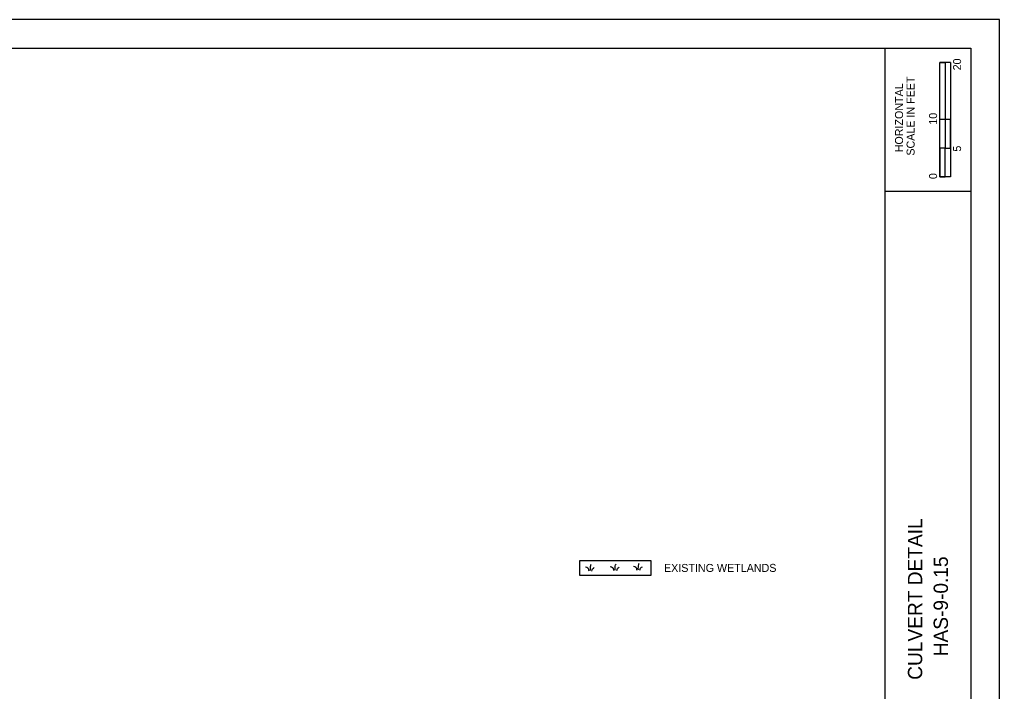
# Model space of a CAD drawing. Extents: x -0.3 to 34, y 0 to 22.
# Drawn here: x 16.87 to 34, y 10.25 to 22 of the extents above; entities that cross this region are included whole.
import ezdxf

# ---------------------------------------------------------------- set-up
doc = ezdxf.new("R2010")
doc.units = 0
for name, color, linetype in [('EV_Ecological_Wetlands', 7, 'Continuous'), ('SH_Border', 7, 'Continuous'), ('SH_Cut_Line', 7, 'Continuous'), ('SH_Data', 7, 'Continuous'), ('SH_Text', 7, 'Continuous')]:
    doc.layers.add(name, color=color, linetype=linetype)

msp = doc.modelspace()

# ---------------------------------------------------------------- linework, layer by layer
at = {"layer": 'EV_Ecological_Wetlands'}
msp.add_lwpolyline([(26.659, 12.535), (26.659, 12.285), (27.909, 12.285), (27.909, 12.535)], close=True, dxfattribs=at)
for points in [[(26.76, 12.43), (26.801, 12.413), (26.819, 12.359)], [(26.847, 12.363), (26.847, 12.411), (26.853, 12.455), (26.862, 12.476)], [(26.875, 12.356), (26.887, 12.395), (26.916, 12.418)], [(27.195, 12.437), (27.236, 12.419), (27.254, 12.366)], [(27.282, 12.37), (27.282, 12.417), (27.288, 12.462), (27.297, 12.483)], [(27.31, 12.363), (27.322, 12.401), (27.351, 12.425)], [(27.599, 12.444), (27.641, 12.426), (27.658, 12.373)], [(27.686, 12.377), (27.686, 12.424), (27.692, 12.469), (27.701, 12.489)], [(27.714, 12.37), (27.726, 12.408), (27.756, 12.432)]]:
    msp.add_spline(points, degree=3, dxfattribs=at)
at = {"layer": 'SH_Border'}
for p, q in [((32, 0.5), (32, 21.5)), ((32, 19), (33.5, 19))]:
    msp.add_line(p, q, dxfattribs=at)
msp.add_lwpolyline([(1.5, 21.5), (33.5, 21.5), (33.5, 0.5), (1.5, 0.5)], close=True, dxfattribs=at)
at = {"layer": 'SH_Cut_Line'}
msp.add_lwpolyline([(0, 0), (34, 0), (34, 22), (0, 22)], close=True, dxfattribs=at)
at = {"layer": 'SH_Data'}
for p, q in [((32.957, 19.25), (32.957, 21.25)), ((33.144, 21.25), (32.957, 21.25)), ((32.957, 20.25), (32.957, 21.25)), ((32.957, 21.25), (33.05, 21.25)), ((33.05, 21.25), (33.051, 21.25)), ((33.051, 21.25), (33.051, 20.25)), ((33.144, 21.25), (33.144, 19.25)), ((33.051, 20.25), (32.957, 20.25)), ((33.143, 20.25), (33.05, 20.25)), ((33.05, 20.25), (33.05, 19.75)), ((33.143, 19.75), (33.143, 20.25)), ((33.05, 19.75), (32.957, 19.75)), ((32.957, 19.75), (32.957, 19.25)), ((33.05, 19.25), (33.05, 19.75)), ((33.05, 19.75), (33.143, 19.75)), ((33.144, 19.25), (32.957, 19.25)), ((32.957, 19.25), (33.05, 19.25))]:
    msp.add_line(p, q, dxfattribs=at)

# ---------------------------------------------------------------- texts
for s, height, p in [('20', 0.14, (33.33, 21.112)), ('SCALE IN FEET', 0.14, (32.517, 19.621)), ('HORIZONTAL', 0.14, (32.315, 19.679)), ('10', 0.14, (32.91, 20.162)), ('5', 0.14, (33.33, 19.691)), ('0', 0.14, (32.91, 19.211)), ('CULVERT DETAIL', 0.25, (32.65, 10.454)), ('HAS-9-0.15', 0.25, (33.1, 10.865))]:
    msp.add_text(s, height=height, rotation=90, dxfattribs=at).set_placement(p)
at = {"layer": 'SH_Text'}
msp.add_text('EXISTING WETLANDS', height=0.14, rotation=0.0251, dxfattribs=at).set_placement((28.135, 12.34))

doc.saveas('drawing.dxf')
